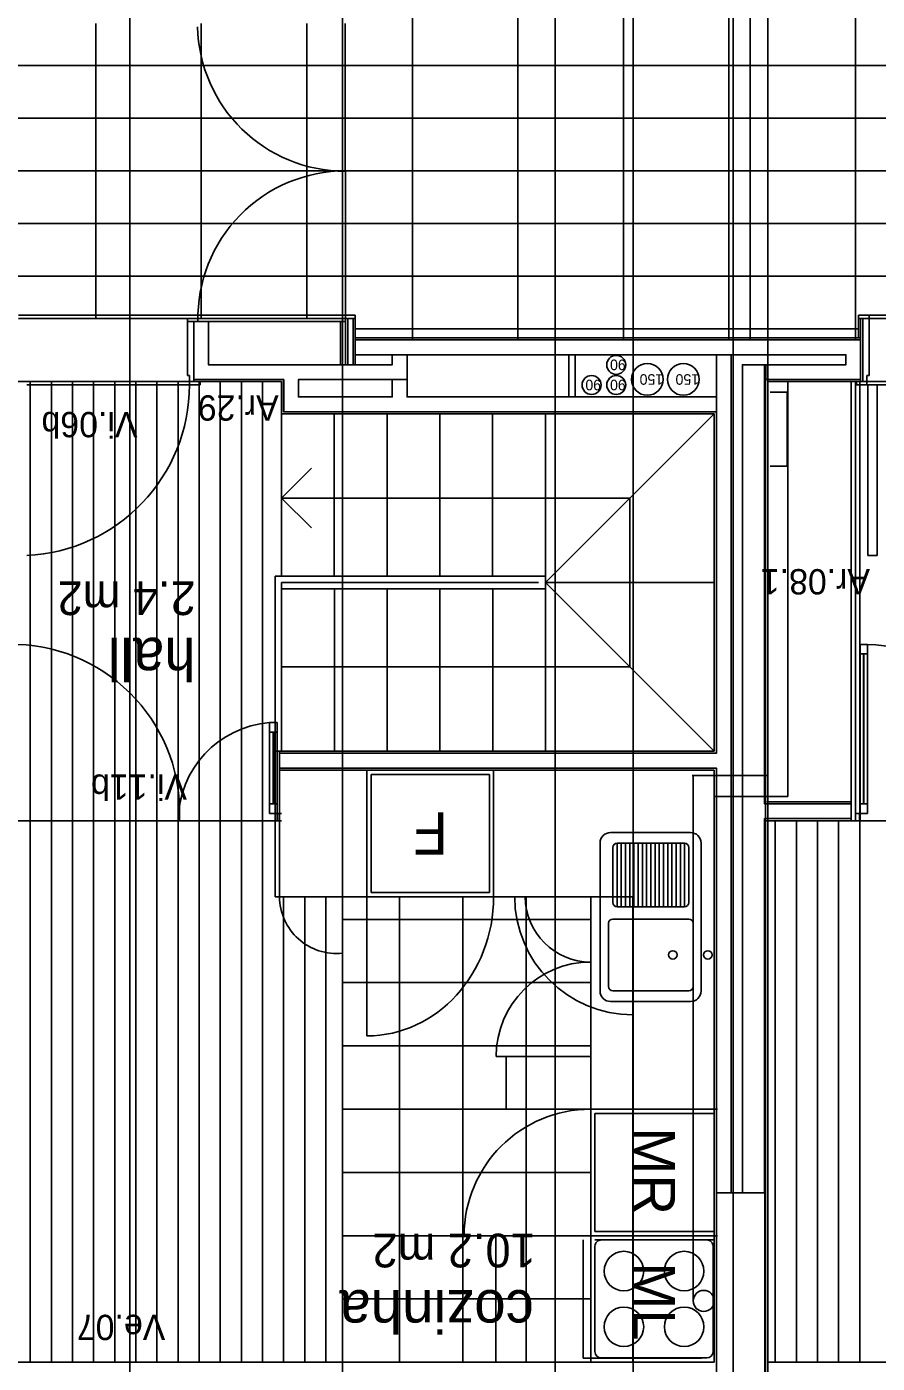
# Model space of a CAD drawing. Extents: x 1248 to 1356, y -443 to -224.
# Drawn here: x 1304.09 to 1308.12, y -243.58 to -237.24 of the extents above; entities that cross this region are included whole.
import ezdxf

# ---------------------------------------------------------------- set-up
doc = ezdxf.new("R2010")
doc.units = 0
for name, color, linetype in [('corte', 7, 'Continuous'), ('estereoctomias', 7, 'Continuous'), ('Level 1', 7, 'Continuous'), ('Level 10', 7, 'Continuous'), ('Level 11', 7, 'Continuous'), ('Level 13', 7, 'Continuous'), ('Level 2', 7, 'Continuous'), ('Level 3', 7, 'Continuous'), ('Level 36', 7, 'Continuous'), ('Level 4', 7, 'Continuous'), ('Level 40', 7, 'Continuous'), ('Level 41', 7, 'Continuous'), ('Level 59', 7, 'Continuous'), ('Level 60', 7, 'Continuous'), ('mob-fixo', 7, 'Continuous'), ('projeccao', 7, 'Continuous'), ('revestimentos', 7, 'Continuous'), ('vermelhos-cont', 7, 'Continuous'), ('vermelhos-tracej', 7, 'Continuous')]:
    doc.layers.add(name, color=color, linetype=linetype)

msp = doc.modelspace()

# ---------------------------------------------------------------- linework, layer by layer
at = {"layer": 'corte'}
for p, q in [((1304.8823, -238.914), (1304.8823, -238.639)), ((1304.9523, -238.844), (1304.9523, -238.639)), ((1305.6473, -238.7963), (1305.8231, -238.7963)), ((1306.659, -238.7963), (1306.659, -238.9963)), ((1306.689, -238.7963), (1306.689, -238.9963)), ((1307.359, -238.9963), (1307.359, -238.7963)), ((1307.429, -242.7713), (1307.429, -238.7963)), ((1304.9523, -238.844), (1305.8231, -238.844)), ((1307.4819, -238.844), (1307.4819, -242.7713)), ((1307.5919, -243.914), (1307.5919, -238.844)), ((1304.8823, -238.914), (1305.3083, -238.914)), ((1305.3083, -239.0663), (1305.3083, -238.914)), ((1305.3783, -238.9963), (1305.3783, -238.914)), ((1305.3783, -238.914), (1305.8231, -238.914)), ((1305.3783, -238.9963), (1305.8231, -238.9963)), ((1305.8931, -238.9963), (1307.3038, -238.9963)), ((1305.8931, -238.9963), (1307.3038, -238.9963)), ((1305.8931, -238.9963), (1307.359, -238.9963)), ((1307.359, -240.6863), (1307.359, -239.0663)), ((1307.359, -242.7713), (1307.359, -240.7563))]:
    msp.add_line(p, q, dxfattribs=at)
msp.add_lwpolyline([(1307.359, -243.7713), (1307.589, -243.7713), (1307.589, -242.7713), (1307.359, -242.7713)], close=True, dxfattribs=at)
at = {"layer": 'estereoctomias'}
for p, q in [((1304.8523, -238.624), (1304.0523, -238.624)), ((1308.0819, -238.624), (1308.8819, -238.624))]:
    msp.add_line(p, q, dxfattribs=at)
for points in [[(1307.3594, -239.0663), (1305.3087, -239.0663), (1305.3087, -238.914), (1304.8823, -238.914), (1304.8823, -238.639), (1304.9523, -238.639), (1304.9523, -238.844), (1305.8231, -238.844), (1305.8231, -238.7963), (1305.8931, -238.7963), (1305.8931, -238.914), (1305.3787, -238.914), (1305.3787, -238.9963), (1305.8231, -238.9963), (1305.8231, -238.914), (1305.8931, -238.914), (1305.8931, -238.9963), (1306.6594, -238.9963), (1306.6594, -238.7963), (1306.6894, -238.7963), (1306.6894, -238.9963), (1307.3594, -238.9963)], [(1305.6473, -238.7263), (1305.6473, -238.7963), (1307.9723, -238.7963), (1307.9723, -238.844), (1307.5923, -238.844), (1307.5923, -238.914), (1308.0423, -238.914), (1308.0423, -238.7263)], [(1307.429, -242.7713), (1307.359, -242.7713), (1307.359, -240.7563), (1305.289, -240.7563), (1305.289, -240.6863), (1307.359, -240.6863), (1307.359, -238.7963), (1307.6034, -238.7963), (1307.429, -238.7963), (1307.429, -242.7713)], [(1307.4819, -242.7713), (1307.5875, -242.7713), (1307.5875, -240.9963), (1307.9975, -240.9963), (1307.9975, -240.9263), (1307.5875, -240.9263), (1307.5875, -238.844), (1307.4819, -238.844)]]:
    msp.add_lwpolyline(points, close=True, dxfattribs=at)
at = {"layer": 'Level 1'}
for p, q in [((1304.9523, -238.639), (1304.8823, -238.639)), ((1305.6473, -238.7263), (1305.6473, -238.7963)), ((1307.6038, -238.7263), (1305.6473, -238.7263)), ((1307.3738, -238.7263), (1308.0419, -238.7263)), ((1308.0419, -238.924), (1308.0419, -238.7163)), ((1305.8231, -238.7963), (1305.8231, -238.844)), ((1307.359, -238.7963), (1305.8931, -238.7963)), ((1305.8931, -238.7963), (1305.8931, -238.9963)), ((1307.429, -238.7963), (1307.9719, -238.7963)), ((1307.9719, -238.844), (1307.9719, -238.7963)), ((1307.4819, -238.844), (1307.9719, -238.844)), ((1305.8231, -238.914), (1305.8231, -238.9963)), ((1307.5919, -238.914), (1308.0419, -238.914)), ((1307.359, -239.0663), (1305.3083, -239.0663)), ((1305.289, -240.6863), (1305.289, -240.7563)), ((1307.359, -240.6863), (1305.289, -240.6863)), ((1307.359, -240.7563), (1305.289, -240.7563)), ((1307.9975, -240.9263), (1307.5875, -240.9263)), ((1307.9975, -240.9163), (1307.9975, -241.0063)), ((1307.5875, -240.9963), (1307.9975, -240.9963))]:
    msp.add_line(p, q, dxfattribs=at)
at = {"layer": 'Level 10'}
for p, q in [((1305.9183, -237.124), (1305.9183, -238.724)), ((1306.4183, -237.124), (1306.4183, -238.724)), ((1306.9183, -237.124), (1306.9183, -238.724)), ((1307.4183, -237.124), (1307.4183, -238.724)), ((1307.5183, -237.124), (1307.5183, -238.724)), ((1308.0183, -237.124), (1308.0183, -238.724)), ((1304.4183, -237.2259), (1304.4183, -238.624)), ((1304.9183, -237.2259), (1304.9183, -238.624)), ((1305.4183, -237.2259), (1305.4183, -238.624)), ((1296.6633, -237.424), (1318.1944, -237.424)), ((1299.1415, -237.674), (1318.1944, -237.674)), ((1299.1415, -237.924), (1318.1944, -237.924)), ((1299.1415, -238.174), (1318.1944, -238.174)), ((1296.6333, -238.424), (1309.5183, -238.424)), ((1305.6473, -238.674), (1308.0319, -238.674)), ((1304.8623, -238.924), (1304.0323, -238.924)), ((1304.1081, -243.574), (1304.1081, -238.924)), ((1304.2081, -243.574), (1304.2081, -238.924)), ((1304.3081, -243.574), (1304.3081, -238.924)), ((1304.4081, -243.574), (1304.4081, -238.924)), ((1304.5081, -243.574), (1304.5081, -238.924)), ((1304.6081, -243.574), (1304.6081, -238.924)), ((1304.7081, -243.574), (1304.7081, -238.924)), ((1304.8081, -243.574), (1304.8081, -238.924)), ((1304.9081, -243.574), (1304.9081, -238.924)), ((1305.0081, -243.574), (1305.0081, -238.924)), ((1305.1081, -243.574), (1305.1081, -238.924)), ((1305.2081, -243.574), (1305.2081, -238.924)), ((1308.0377, -240.9713), (1308.0377, -238.924)), ((1308.8819, -238.924), (1308.0619, -238.924)), ((1307.6377, -243.574), (1307.6377, -241.0063)), ((1307.7377, -243.574), (1307.7377, -241.0063)), ((1307.8377, -243.574), (1307.8377, -241.0063)), ((1307.9377, -243.574), (1307.9377, -241.0063)), ((1308.0377, -243.574), (1308.0377, -241.0063)), ((1305.3081, -243.574), (1305.3081, -241.3663)), ((1305.4081, -243.574), (1305.4081, -241.3663)), ((1305.5081, -243.574), (1305.5081, -241.3663)), ((1305.5873, -243.574), (1305.5873, -241.3663)), ((1305.8581, -243.574), (1305.8581, -241.3663)), ((1306.1581, -243.574), (1306.1581, -241.3663)), ((1306.4581, -243.574), (1306.4581, -241.3663)), ((1306.7633, -241.474), (1305.5873, -241.474)), ((1306.7633, -241.774), (1305.5873, -241.774)), ((1306.7633, -242.074), (1305.5873, -242.074)), ((1306.7633, -242.374), (1305.5873, -242.374)), ((1306.7633, -242.674), (1305.5873, -242.674)), ((1306.7633, -242.974), (1305.5873, -242.974)), ((1306.7633, -243.274), (1305.5873, -243.274))]:
    msp.add_line(p, q, dxfattribs=at)
at = {"layer": 'Level 11'}
for p, q in [((1305.7231, -241.3463), (1305.7231, -240.7863)), ((1305.7231, -240.7863), (1306.2831, -240.7863)), ((1306.2831, -241.3463), (1306.2831, -240.7863)), ((1306.8684, -241.3939), (1306.8684, -241.1324)), ((1307.2084, -241.1124), (1306.8884, -241.1124)), ((1306.8884, -241.4139), (1306.8884, -241.1124)), ((1306.9084, -241.4139), (1306.9084, -241.1124)), ((1306.9284, -241.4139), (1306.9284, -241.1124)), ((1306.9484, -241.4139), (1306.9484, -241.1124)), ((1306.9684, -241.4139), (1306.9684, -241.1124)), ((1306.9884, -241.4139), (1306.9884, -241.1124)), ((1307.0084, -241.4139), (1307.0084, -241.1124)), ((1307.0284, -241.4139), (1307.0284, -241.1124)), ((1307.0484, -241.4139), (1307.0484, -241.1124)), ((1307.0684, -241.4139), (1307.0684, -241.1124)), ((1307.0884, -241.4139), (1307.0884, -241.1124)), ((1307.1084, -241.4139), (1307.1084, -241.1124)), ((1307.1284, -241.4139), (1307.1284, -241.1124)), ((1307.1484, -241.4139), (1307.1484, -241.1124)), ((1307.1684, -241.4139), (1307.1684, -241.1124)), ((1307.1884, -241.4139), (1307.1884, -241.1124)), ((1307.2084, -241.4139), (1307.2084, -241.1124)), ((1307.2284, -241.3939), (1307.2284, -241.1324)), ((1306.2831, -241.3463), (1305.7231, -241.3463)), ((1307.2084, -241.4139), (1306.8884, -241.4139)), ((1306.8684, -241.4724), (1307.2284, -241.4724)), ((1306.8484, -241.7924), (1306.8484, -241.4924)), ((1307.2484, -241.4924), (1307.2484, -241.7924)), ((1307.2284, -241.8124), (1306.8684, -241.8124)), ((1306.8133, -242.9939), (1307.3133, -242.9939)), ((1306.7833, -243.0239), (1306.7833, -243.5239)), ((1307.3433, -243.0239), (1307.3433, -243.5239)), ((1306.8133, -243.5539), (1307.3133, -243.5539))]:
    msp.add_line(p, q, dxfattribs=at)
for points in [[(1307.2362, -241.0621), (1306.8578, -241.0621)], [(1306.8078, -241.1121), (1306.8078, -241.8136)], [(1307.2862, -241.8136), (1307.2862, -241.1121)], [(1306.8578, -241.8636), (1307.2362, -241.8636)]]:
    msp.add_lwpolyline(points, dxfattribs=at)
for centre, radius in [((1307.1524, -241.6424), 0.0199), ((1307.3183, -241.6424), 0.0199), ((1306.9207, -243.1417), 0.0936), ((1307.2059, -243.1417), 0.0936), ((1306.9207, -243.406), 0.0936), ((1307.2059, -243.406), 0.0936)]:
    msp.add_circle(centre, radius, dxfattribs=at)
for centre, radius, start, end in [((1306.8578, -241.1121), 0.05, 90, 180), ((1307.2362, -241.1121), 0.05, 0, 90), ((1306.8884, -241.1324), 0.02, 90, 180), ((1307.2084, -241.1324), 0.02, 360, 90), ((1306.8884, -241.3939), 0.02, 180, 270), ((1307.2084, -241.3939), 0.02, 270, 360), ((1306.8684, -241.4924), 0.02, 90, 180), ((1307.2284, -241.4924), 0.02, 360, 90), ((1306.8684, -241.7924), 0.02, 180, 270), ((1307.2284, -241.7924), 0.02, 270, 0), ((1306.8578, -241.8135), 0.05, 180, 270), ((1307.2362, -241.8135), 0.05, 270, 0), ((1306.8133, -243.0239), 0.03, 89.9999, 179.99991), ((1307.3133, -243.0239), 0.03, 359.9998, 90.00015), ((1306.8133, -243.5239), 0.03, 179.99998, 269.99995), ((1307.3133, -243.5239), 0.03, 270.00001, 359.99979)]:
    msp.add_arc(centre, radius, start, end, dxfattribs=at)
at = {"layer": 'Level 13'}
for p, q in [((1304.8523, -238.639), (1304.8523, -238.624)), ((1304.9023, -238.624), (1304.8523, -238.624)), ((1305.6023, -238.624), (1304.8923, -238.624)), ((1305.6023, -238.624), (1304.8923, -238.624)), ((1305.6023, -238.624), (1304.9023, -238.624)), ((1304.9023, -238.639), (1304.9023, -238.624)), ((1305.6023, -238.624), (1305.6023, -238.609)), ((1305.6023, -238.609), (1305.6473, -238.609)), ((1305.6023, -238.639), (1305.6023, -238.624)), ((1305.6023, -238.624), (1305.6473, -238.624)), ((1305.6023, -238.844), (1305.6023, -238.624)), ((1305.6123, -238.624), (1305.6123, -238.844)), ((1305.6373, -238.624), (1305.6373, -238.844)), ((1305.6473, -238.624), (1305.6473, -238.609)), ((1305.6473, -238.644), (1305.6473, -238.624)), ((1308.0319, -238.609), (1308.0319, -238.7163)), ((1308.0819, -238.609), (1308.0319, -238.609)), ((1308.0319, -238.624), (1308.0819, -238.624)), ((1308.0419, -238.7163), (1308.0419, -238.624)), ((1308.0519, -238.924), (1308.0519, -238.624)), ((1308.0819, -238.624), (1308.0819, -238.609)), ((1308.0819, -238.895), (1308.0819, -238.624)), ((1304.8523, -238.639), (1304.8523, -238.895)), ((1305.6023, -238.639), (1304.8523, -238.639)), ((1304.8823, -238.924), (1304.8823, -238.639)), ((1305.6473, -238.644), (1305.6473, -238.844)), ((1304.8523, -238.895), (1304.8623, -238.895)), ((1304.8623, -238.895), (1304.8623, -238.924)), ((1307.9975, -240.9163), (1307.9975, -238.924)), ((1308.0175, -241.0063), (1308.0175, -238.924)), ((1308.0819, -238.895), (1308.0719, -238.895)), ((1308.0719, -238.895), (1308.0719, -238.924)), ((1308.0769, -239.749), (1308.0769, -238.939)), ((1308.0769, -238.939), (1308.1209, -238.939)), ((1308.1209, -238.939), (1308.1209, -239.749)), ((1308.1209, -239.749), (1308.0769, -239.749)), ((1308.0395, -240.9713), (1308.0395, -240.1704)), ((1308.0745, -240.1704), (1308.0395, -240.1704)), ((1308.0745, -240.9713), (1308.0745, -240.1704)), ((1308.0745, -240.2154), (1308.0395, -240.2154)), ((1305.277, -240.541), (1305.242, -240.541)), ((1305.242, -240.9713), (1305.242, -240.541)), ((1305.277, -240.586), (1305.242, -240.586)), ((1305.277, -240.9713), (1305.277, -240.541)), ((1305.269, -240.6763), (1305.269, -241.3663)), ((1305.289, -240.6763), (1305.269, -240.6763)), ((1305.289, -240.6763), (1305.289, -241.3663)), ((1305.242, -240.9263), (1305.277, -240.9263)), ((1305.242, -240.9713), (1305.277, -240.9713)), ((1305.279, -240.9713), (1305.279, -241.0063)), ((1305.279, -240.9713), (1305.299, -240.9713)), ((1308.0375, -240.9713), (1308.0175, -240.9713)), ((1308.0375, -241.0063), (1308.0375, -240.9713)), ((1308.0745, -240.9263), (1308.0395, -240.9263)), ((1308.0745, -240.9713), (1308.0395, -240.9713)), ((1305.279, -241.0063), (1305.299, -241.0063)), ((1308.0175, -241.0063), (1307.9975, -241.0063)), ((1308.0375, -241.0063), (1308.0175, -241.0063)), ((1305.269, -241.3663), (1305.289, -241.3663))]:
    msp.add_line(p, q, dxfattribs=at)
for points in [[(1304.9123, -238.939), (1304.8623, -238.939), (1304.8623, -238.924), (1304.9123, -238.924)], [(1308.0219, -238.939), (1308.0719, -238.939), (1308.0719, -238.924), (1308.0219, -238.924)]]:
    msp.add_lwpolyline(points, close=True, dxfattribs=at)
at = {"layer": 'Level 2'}
for p, q in [((1305.2983, -239.0763), (1305.2983, -239.8463)), ((1305.5483, -239.0763), (1305.5483, -239.8463)), ((1305.7983, -239.0763), (1305.7983, -239.8463)), ((1306.0483, -239.0763), (1306.0483, -239.8463)), ((1306.2983, -239.0763), (1306.2983, -239.8463)), ((1306.549, -239.0763), (1306.549, -239.8463)), ((1306.549, -239.8763), (1307.349, -239.0763)), ((1305.4397, -239.3349), (1305.2983, -239.4763)), ((1306.949, -239.4763), (1305.2983, -239.4763)), ((1305.4397, -239.6177), (1305.2983, -239.4763)), ((1306.949, -239.4763), (1306.949, -240.2763)), ((1306.549, -239.8463), (1305.269, -239.8463)), ((1305.269, -240.6763), (1305.269, -239.8463)), ((1306.5166, -239.8763), (1305.2983, -239.8763)), ((1305.299, -240.6763), (1305.299, -239.8763)), ((1306.549, -239.9063), (1306.549, -239.8463)), ((1307.349, -239.8763), (1306.549, -239.8763)), ((1306.549, -239.8763), (1307.349, -240.6763)), ((1306.549, -239.9063), (1305.299, -239.9063)), ((1305.549, -239.9063), (1305.549, -240.6763)), ((1305.799, -239.9063), (1305.799, -240.6763)), ((1306.049, -239.9063), (1306.049, -240.6763)), ((1306.299, -239.9063), (1306.299, -240.6763)), ((1306.549, -239.9063), (1306.549, -240.6763)), ((1305.299, -240.2763), (1306.949, -240.2763)), ((1305.7031, -241.3663), (1305.7031, -240.7663)), ((1306.3031, -241.3663), (1306.3031, -240.7663)), ((1306.7633, -241.3663), (1305.289, -241.3663)), ((1306.7633, -241.3663), (1305.4581, -241.3663)), ((1306.7633, -241.3663), (1305.4581, -241.3663)), ((1306.7633, -243.574), (1306.7633, -241.3663)), ((1305.5873, -243.574), (1303.5723, -243.574)), ((1309.6173, -243.574), (1307.6019, -243.574))]:
    msp.add_line(p, q, dxfattribs=at)
at = {"layer": 'Level 3'}
for p, q in [((1306.9633, -241.3663), (1306.7633, -241.3663)), ((1306.9633, -243.574), (1306.9633, -241.3663))]:
    msp.add_line(p, q, dxfattribs=at)
at = {"layer": 'Level 36'}
for p, q in [((1308.056, -240.9263), (1308.056, -240.2154)), ((1308.058, -240.9263), (1308.058, -240.2154)), ((1305.2585, -240.9263), (1305.2585, -240.586)), ((1305.2605, -240.9263), (1305.2605, -240.586))]:
    msp.add_line(p, q, dxfattribs=at)
at = {"layer": 'Level 4'}
for p, q in [((1305.6004, -237.2259), (1305.6004, -237.9259)), ((1305.6023, -238.624), (1305.6023, -237.924)), ((1304.0523, -238.609), (1305.6023, -238.609)), ((1308.0819, -238.609), (1309.6319, -238.609)), ((1305.5773, -238.844), (1305.5773, -238.639)), ((1304.8623, -238.939), (1304.0913, -238.939)), ((1308.8919, -238.939), (1308.1209, -238.939)), ((1307.6138, -238.974), (1307.6938, -238.974)), ((1307.6938, -239.324), (1307.6938, -238.974)), ((1307.6138, -239.324), (1307.6938, -239.324)), ((1305.5873, -241.6339), (1305.5873, -240.7663)), ((1305.277, -240.9713), (1305.277, -241.0063)), ((1308.0395, -240.9713), (1308.0395, -241.0063)), ((1304.0075, -241.0063), (1305.299, -241.0063)), ((1308.0375, -241.0063), (1309.329, -241.0063)), ((1305.7031, -242.0263), (1305.7031, -241.3663)), ((1306.7633, -242.1243), (1306.3153, -242.1243)), ((1306.3633, -242.374), (1306.3633, -242.1243)), ((1306.7633, -242.374), (1306.3081, -242.374)), ((1306.7633, -242.374), (1307.3633, -242.374)), ((1306.7833, -242.394), (1307.3433, -242.394)), ((1306.7833, -242.394), (1306.7833, -242.954)), ((1306.7633, -242.974), (1306.1081, -242.974)), ((1306.3133, -242.974), (1306.3133, -243.574)), ((1306.7281, -243.554), (1306.7281, -242.994)), ((1307.3633, -242.974), (1306.7633, -242.974)), ((1306.7833, -242.954), (1307.3433, -242.954)), ((1307.3433, -242.994), (1306.7833, -242.994)), ((1307.2881, -243.554), (1306.7281, -243.554))]:
    msp.add_line(p, q, dxfattribs=at)
for centre, radius, start, end in [((1305.6004, -237.2259), 0.7, 181.22786, 270), ((1305.6023, -238.624), 0.7, 90, 181.22786), ((1306.9633, -241.3663), 0.56, 180, 270), ((1306.7633, -241.3663), 0.31, 180, 270), ((1306.7633, -242.1243), 0.448, 90, 180), ((1306.7633, -242.974), 0.6, 90, 180)]:
    msp.add_arc(centre, radius, start, end, dxfattribs=at)
for centre, major_axis, ratio, start_param in [((1304.0563, -238.939), (0, -0.81), 0.995105, 0.043492), ((1305.7031, -241.3663), (0, -0.66), 0.909091, 0)]:
    msp.add_ellipse(centre, major_axis=major_axis, ratio=ratio, start_param=start_param, end_param=1.570796, dxfattribs=at)
at = {"layer": 'Level 41'}
for centre, radius in [((1306.8843, -238.8443), 0.045), ((1307.0316, -238.9135), 0.075), ((1307.2018, -238.9135), 0.075), ((1306.7675, -238.9397), 0.045), ((1306.8843, -238.9397), 0.045)]:
    msp.add_circle(centre, radius, dxfattribs=at)
at = {"layer": 'Level 59'}
msp.add_lwpolyline([(1312.108, -245.3846), (1306.9649, -245.3846), (1306.9649, -230.4331), (1312.108, -230.4331)], close=True, dxfattribs=at)
at = {"layer": 'mob-fixo'}
for p, q in [((1307.6975, -238.924), (1307.6975, -240.8913)), ((1307.2446, -240.7913), (1307.5975, -240.7913)), ((1307.249, -243.2833), (1307.249, -240.7913)), ((1307.3446, -240.8913), (1307.6975, -240.8913))]:
    msp.add_line(p, q, dxfattribs=at)
msp.add_circle((1307.299, -243.2833), 0.05, dxfattribs=at)
at = {"layer": 'projeccao'}
for centre, radius, start, end in [((1304.0196, -240.9656), 0.7962, 357.07034, 87.89077), ((1308.0452, -240.9656), 0.7962, 357.07034, 87.89077), ((1305.277, -241.0063), 0.4666, 94.30164, 180)]:
    msp.add_arc(centre, radius, start, end, dxfattribs=at)
msp.add_ellipse((1305.5581, -241.3663), major_axis=(0, -0.2692), ratio=0.999336, start_param=4.712389, end_param=6.39211, dxfattribs=at)
at = {"layer": 'revestimentos'}
for p, q in [((1307.6038, -238.7163), (1305.6473, -238.7163)), ((1307.3738, -238.7163), (1308.0419, -238.7163)), ((1304.9123, -238.924), (1305.2983, -238.924)), ((1305.2983, -239.0763), (1305.2983, -238.924)), ((1307.6019, -238.924), (1308.0338, -238.924)), ((1307.6019, -240.9163), (1307.6019, -238.924)), ((1305.2983, -239.0763), (1307.349, -239.0763)), ((1307.349, -240.6763), (1307.349, -239.0763)), ((1307.349, -240.6763), (1305.289, -240.6763)), ((1307.349, -240.7663), (1305.289, -240.7663)), ((1307.349, -243.574), (1307.349, -240.7663)), ((1307.9975, -240.9163), (1307.5975, -240.9163)), ((1307.5968, -241.0063), (1307.9975, -241.0063)), ((1307.6019, -243.924), (1307.6019, -241.0063)), ((1305.5873, -243.574), (1305.5873, -243.924)), ((1307.349, -243.574), (1305.5873, -243.574))]:
    msp.add_line(p, q, dxfattribs=at)
at = {"layer": 'vermelhos-cont'}
msp.add_line((1307.439, -250.7923), (1307.439, -229.6198), dxfattribs=at)
at = {"layer": 'vermelhos-tracej'}
for p, q in [((1304.5798, -246.757), (1304.5798, -236.1407)), ((1305.5873, -246.757), (1305.5873, -236.1407)), ((1306.5948, -246.757), (1306.5948, -236.1407)), ((1307.6023, -246.757), (1307.6023, -236.1407))]:
    msp.add_line(p, q, dxfattribs=at)

# ---------------------------------------------------------------- texts
at = {"layer": 'Level 11'}
for s, rotation, p in [('F', 180, (1306.087, -240.9663)), ('MR', 270, (1306.9633, -242.4603)), ('ML', 270, (1306.9633, -243.1))]:
    msp.add_text(s, height=0.2, rotation=rotation, dxfattribs=at).set_placement(p)
at = {"layer": 'Level 40'}
for s, p in [('Ar.29', (1305.2851, -238.9888)), ('Vi.06b', (1304.6162, -239.0676)), ('Ar.08.1', (1308.0865, -239.8129)), ('Vi.11b', (1304.8507, -240.7869)), ('Ve.07', (1304.7479, -243.3489))]:
    msp.add_text(s, height=0.12, rotation=180.00001, dxfattribs=at).set_placement(p)
at = {"layer": 'Level 41'}
for s, p in [('90', (1306.9293, -238.8193)), ('90', (1306.8125, -238.9147)), ('90', (1306.9293, -238.9147)), ('150', (1307.1066, -238.8885)), ('150', (1307.2768, -238.8885))]:
    msp.add_text(s, height=0.05, rotation=180, dxfattribs=at).set_placement(p)
at = {"layer": 'Level 60'}
for s, height, p in [('2.4 m2', 0.16, (1304.8917, -239.8708)), ('hall', 0.2, (1304.8917, -240.1386)), ('10.2 m2', 0.16, (1306.5027, -242.9642)), ('cozinha', 0.2, (1306.4941, -243.232))]:
    msp.add_text(s, height=height, rotation=180, dxfattribs=at).set_placement(p)

doc.saveas('drawing.dxf')
